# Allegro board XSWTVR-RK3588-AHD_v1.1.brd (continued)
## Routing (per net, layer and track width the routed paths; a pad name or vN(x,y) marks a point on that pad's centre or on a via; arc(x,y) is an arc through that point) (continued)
N17604223: length 3.4
  TOP w0.127: C345.2 78.73,20.72 U25.1
N17604225: length 3.1
  TOP w0.127: C346.1 78.08,16.91 U25.4
N17604227: length 3.1
  TOP w0.127: U25.5 78.08,15.64 C346.2
N17604259: length 2.2
  TOP w0.127: U25.2 79.3,19.45 C347.2
N17604261: length 2.2
  TOP w0.127: C348.1 78.82,14.37 U25.6
N17613828: length 2.1
  TOP w0.127: R308.1 78.89,13.1 U25.7
N17613831: length 2.2
  TOP w0.127: U25.8 79,11.83 R309.1
N17622103: length 35.2
  BOTTOM w0.127: R66.1 30.41,33.19 30.41,38.02 30.96,38.57 35.18,38.57 35.57,38.18 42.75,38.18 49.94,45.36 49.94,47.09 50.25,47.4 Q3.1 52.37,47.4 R64.2 52.69,47.54 C108.2
N17622132: length 1.1
  BOTTOM w0.127: R66.2 31.49,30.66 Q5.3
N17622163: length 3.4
  BOTTOM w0.127: 27.69,28.82 R68.2 ; 27.69,28.82 R70.1 C110.1 ; 27.69,28.82 28.88,28.82 Q5.1
N17627462: length 1.8
  TOP w0.127: R129.2 77.65,138.72 77.65,138.72 U14.44
N17719071: length 2.3
  TOP w0.127: R2.1 42.98,48.84 U1.59
N17720124: length 2.9
  TOP w0.127: SW1.1 38.85,100.52 38.85,101.89 R1.2
N17720923: length 2.6
  TOP w0.381: R305.2 R304.1 55.46,130.28 Q30.1
N17726410: length 4.8
  TOP w0.203: R258.2 54.49,113.65 C325.1 53.49,112.73 R257.1 53.13,113.09 53.13,113.96 C329.1 54.17,113.97 R258.2
N17726460: length 1.8
  TOP w0.203: C326.2 52,115.17 U23.22
N17726498: length 3.8
  TOP w0.203: C328.2 52.24,113.41 C329.2 50.25,113.97 49.95,114.27 U23.21
N17732255: length 4.6
  BOTTOM w0.127: R63.2 12.9,40.23 13.42,39.7 Q2.1 ; R63.2 12.06,40.22 R65.1 ; R63.2 11.12,40.23 C106.2
N17732284: length 1.7
  BOTTOM w0.127: R65.2 12.06,37.5 Q4.3
N17732315: length 3.7
  BOTTOM w0.127: Q4.1 17.31,38.45 R69.1 17.76,37.99 C109.1 19.68,37.99 R67.2
N17733329: length 1.8
  TOP w0.127: U8.23 105.17,30.85 105.18,30.86 R39.1
N17735210: length 7.6
  TOP w0.127: R253.2 19.33,23.41 17.69,23.41 17.51,23.23 D31.1 17.5,22.89 J22.2
N17735212: length 7.9
  TOP w0.127: J22.3 17.5,23.99 D30.1 17.51,24.54 17.68,24.72 19.12,24.72 R254.2
N17735222: length 7.8
  TOP w0.127: R256.2 19.27,30.03 17.63,30.03 17.51,29.91 D27.1 17.07,29.44 17.02,29.49 13.93,29.49 13.92,29.49 J22.8
N17735246: length 7.6
  TOP w0.127: R252.2 19.31,22.33 17.75,22.33 17.51,22.09 D32.1 17.5,21.79 J22.1
N17735252: length 7.8
  TOP w0.127: J22.5 17.46,26.19 D29.1 17.51,26.72 17.63,26.85 18.95,26.85 19.63,26.17 R359.2
N17735257: length 7.8
  TOP w0.127: R255.2 19.26,28.93 17.63,28.93 17.51,28.8 D28.1 17.46,28.39 J22.7
N17791454: length 3.6
  TOP w0.203: 48.15,114.02 U23.17
  TOP w0.508: FB28.2 48.15,111.06 C335.1 C334.1 48.15,114.02
N17887677: length 9.4
  TOP w0.254: D41.3 64.13,151.37 61.32,151.37 60.22,150.26 R323.1
N17887693: length 5.6
  TOP w0.254: D41.1 64.28,149.01 63.18,149.01 61.2,147.03 R324.1
N17891340: length 1.7
  TOP w0.127: R329.2 34.46,76.8 U28.8
N17893373: length 2.3
  TOP w0.127: R330.2 35.36,78.57 R331.1 35.35,77.6 U28.10
N17901873: length 2.8
  TOP w0.127: R44.2 65.06,23.66 R43.2 67.66,23.66 U9.13
N17901877: length 2.8
  TOP w0.127: U9.12 67.63,24.66 R43.1 65.07,24.66 R45.2
N17904447: length 2.8
  TOP w0.127: U10.13 80.6,23.86 R333.2 78.04,23.86 R332.2
N17904489: length 2.8
  TOP w0.127: R334.2 78.04,24.86 R333.1 80.71,24.86 U10.12
N17906339: length 2.8
  TOP w0.127: R335.2 78.05,33.69 R336.2 80.68,33.69 U26.13
N17906381: length 2.8
  TOP w0.127: U26.12 80.64,34.69 R336.1 78.05,34.69 R337.2
N17907326: length 2.9
  TOP w0.127: R338.2 75.8,38.46 75.76,38.42 R339.2 75.02,38.65 U29.13
N17907351: length 2.8
  TOP w0.127: U29.12 73.46,37.42 R339.1 75.78,37.42 75.8,37.44 R340.2
N17918762: length 3.4
  TOP w0.127: D44.1 115.35,14.14 114.83,14.66 R342.1 114.83,16.6 R341.2
N17918800: length 3.5
  TOP w0.127: R342.2 113.36,16.08 111.24,16.08 111.04,15.88 Q31.1
N17919694: length 5.6
  BOTTOM w0.127: Q32.1 26.48,35.96 26.48,33.03 C376.2 27.7,31.82 R344.2
N17920327: length 2.9
  TOP w0.381: R346.2 95.71,31.73 C377.2 96.37,31.73 97.03,32.38 Q33.1
N17947557: length 7.9
  TOP w0.203: R134.2 89.08,147.31 89.65,147.89 91.02,147.89 91.92,148.79 91.92,151.5 D43.4
N17948062: length 4.5
  TOP w0.203: D43.2 89.12,148.59 88.57,148.59 87.77,147.79 R348.2
N18031326: length 6.3
  TOP w0.127: R206.1 152.75,82.11 151.42,83.45 151.42,86.26 151,86.67 U19.31
N18177282: length 1.5
  TOP w0.127: U9.7 74.5,29.89 R351.2
N18177600: length 1.8
  TOP w0.127: R353.2 88.25,30.02 U10.7
N18177766: length 2
  TOP w0.127: R355.2 87.34,40.47 86.79,39.92 U26.7
N18177976: length 1.7
  TOP w0.102: U29.7 66.53,32.3 66.52,32.29 R357.2
N18179902: length 1.6
  TOP w0.305: C378.1 27.76,30.72 27.75,30.71 U22.1
N18180321: length 3.8
  TOP w0.127: U22.9 24.06,28.07 22.82,29.32 22.82,30.56 R250.2
N18180375: length 4.9
  TOP w0.127: R248.2 21.8,30.44 22.08,30.16 22.08,28.98 23.99,27.07 U22.11
N18180517: length 1.6
  TOP w0.127: U22.14 25.75,25.31 25.9,25.15 R360.2
N18180676: length 1.6
  TOP w0.254: C379.2 26.77,25.3 26.75,25.33 U22.16
N25391738: length 7.5
  TOP w0.203: C343.1 41.35,118.01 41.35,116.92 42.09,116.18 46.56,116.18 U23.12
N25392270: length 2.3
  TOP w0.203: C339.1 49.57,113.26 49.05,113.78 U23.19
N25392272: length 4.3
  TOP w0.254: U23.10 45.49,116.97 44.42,118.04 C340.1
N25392276: length 2.6
  TOP w0.203: C338.1 49.5,114.02 U23.20
N25392525: length 6.8
  TOP w0.203: C344.1 41.74,118.02 41.74,117.1 42.32,116.52 U23.11
N25392529: length 1.8
  TOP w0.127: R260.2 50.54,119.63 49.95,119.04 U23.1
N25392543: length 1.8
  TOP w0.127: R261.2 48.15,119.45 U23.5
N25392545: length 1.6
  TOP w0.127: R262.2 47.7,119.98 47.7,119.17 47.7,119.17 U23.6
N25392559: length 1.8
  TOP w0.127: U23.7 47.25,119.42 R263.2
N25392573: length 2.8
  TOP w0.127: U23.8 46.19,117.87 45.67,118.39 45.67,119.98 R264.2
N25392575: length 1.7
  TOP w0.127: R265.2 52.2,117.87 U23.28
N25392589: length 1.9
  TOP w0.127: R266.2 51.66,117.42 U23.27
N174312303: length 2.1
  TOP w0.203: R25.2 146.39,62.67 146.69,62.37 146.69,61.95 146.2,61.46 U5.4
N175432600: length 1.8
  TOP w0.203: R134.1 90.08,146.73 90.32,146.49 Q12.3

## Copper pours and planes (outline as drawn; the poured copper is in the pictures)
DGND on TOP: 0.51,156 1.53,158.47 4,159.49 155.78,159.49 158.25,158.47 159.27,156 159.27,4 158.25,1.53 155.78,0.51 4,0.51 1.53,1.53 0.51,4 ; 72 cut-outs
DGND on BOTTOM: 155.78,159.49 158.25,158.47 159.27,156 159.27,4 158.25,1.53 155.78,0.51 4,0.51 1.53,1.53 0.51,4 0.51,156 1.53,158.47 4,159.49 ; 48 cut-outs
DGND on GND02, POW04, GND05: 155.78,159.49 158.25,158.47 159.27,156 159.27,4 158.25,1.53 155.78,0.51 4,0.51 1.53,1.53 0.51,4 0.51,156 1.53,158.47 4,159.49
DGND on L3: 0.51,156 1.53,158.47 4,159.49 155.78,159.49 158.25,158.47 159.27,156 159.27,4 158.25,1.53 155.78,0.51 4,0.51 1.53,1.53 0.51,4 ; 21 cut-outs
VCC1V2 on TOP: 57.83,20.14 54.26,20.14 54.07,19.95 54.07,18.38 54.25,18.19 57.49,18.19 57.91,17.78 57.91,15.17 58.78,14.29 58.78,12.14 58.96,11.97 60.85,11.97 61.01,12.12 61.01,14.37 61.82,15.18 61.82,20.37 61.67,20.52 58.21,20.52
VCC1V2 on BOTTOM: 55.45,20.07 54.26,20.07 54.14,19.95 54.14,18.73 54.28,18.59 55.51,18.59 55.56,18.64 55.56,19.96
VCC3V3_SYS on TOP: 61.85,14.54 61.61,14.3 61.61,12.06 61.71,11.95 63.01,11.95 63.11,12.05 63.11,12.73 63.28,12.9 67.29,12.9 67.58,13.19 67.58,15.64 67.41,15.81 65.65,15.81 65.54,15.7 65.54,14.77 65.54,14.76 65.54,14.71 65.37,14.54
VCC3V3_SYS on TOP: 1.03,104.53 0.89,104.4 0.89,101.89 1.01,101.77 6.49,101.77 6.64,101.92 6.64,102.91 6.87,103.13 7.88,103.13 8.01,103.26 8.01,104.41 7.89,104.53
VCC3V3_SYS on BOTTOM: 145.19,39.74 143.01,39.74 142.16,38.88 142.16,37.45 142.38,37.22 144.77,37.22 145.23,37.68 145.23,39.7
VCC3V3_SYS on BOTTOM: 54.99,22 52.99,22 52.92,21.92 52.92,20.79 53,20.71 54.96,20.71 55.04,20.79 55.04,21.95
VCC3V3_SYS on BOTTOM: 139.49,22.09 139.49,20.93 139.41,20.85 137.45,20.85 137.37,20.93 137.37,22.06 137.44,22.14 139.44,22.14
VCC3V3_SYS on BOTTOM: 57.95,33.22 56.81,33.22 56.75,33.16 56.75,31.44 56.83,31.36 57.99,31.36 58.06,31.43 58.06,33.11
VCC3V3_SYS on BOTTOM: 142.55,32.3 142.55,30.63 142.48,30.55 141.32,30.55 141.24,30.63 141.24,32.35 141.3,32.41 142.44,32.41
VCC3V3_SYS on BOTTOM: 149.47,69.07 149.49,69.07 152.64,69.07 152.96,68.75 152.96,67.25 152.96,67.25 153.18,67.03 153.82,67.03 154.49,66.36 154.49,65.08 154.1,64.69 152.39,64.69 152.15,64.93 152.14,66.64 151.65,67.08 149.57,67.08 149.39,67.26 149.39,68.99
VCC3V3_SYS on BOTTOM: 57.28,46.9 50.67,46.9 50.4,46.64 50.4,44.97 50.52,44.85 57.31,44.85 57.61,45.15 57.61,46.58
VCC3V3_SYS on BOTTOM: 7.86,104.65 3.84,104.65 3.71,104.51 3.71,103.2 3.85,103.06 7.91,103.06 8,103.15 8,104.5
VCC3V3_SYS on L3: 148.36,86.77 153.91,86.77 157.83,82.85 157.83,17.64 152.67,12.49 109.51,12.49 105.54,8.52 93.02,8.52 89.05,12.49 80.13,12.49 80.12,12.47 22.54,12.47 19.78,15.23 5.65,15.23 2.21,18.67 2.21,66.12 2.58,66.49 9.52,66.49 9.52,66.5 14.53,66.5 16.97,64.06 16.97,50.57 14.3,47.89 11.08,47.89 10.73,47.55 10.73,22.13 11.93,20.94 19.77,20.94 53.09,20.94 57.82,25.66 69.36,25.66 69.87,25.15 80.8,25.15 81.44,25.78 82.3,25.78 84.98,25.78 85.08,25.9 97.24,25.9 101.92,30.58 127.16,30.58 136.37,39.8 149.31,39.8 150.41,40.9 150.43,52.63 147.02,56.04 147.02,85.43
VCC3V3_SYS on POW04: 1.84,104.49 7.91,104.49 8.46,103.94 8.46,78.42 9.75,77.12 13.44,77.12 15.1,75.47 15.1,67.71 9,61.62 7.55,61.62 7.53,61.6 2.29,61.6 1.36,62.53 1.36,104.02
VCC3V9_5G on TOP: 111.62,61.19 109.54,61.19 109.32,60.98 109.32,57.63 109.51,57.44 112.38,57.44 117.97,63.03 117.97,70.87 117.88,70.95 114.31,70.95 114.25,70.89 114.25,63.81
VCC3V9_5G on BOTTOM: 9.47,47.5 12.86,47.5 12.86,47.14 14.79,45.22 14.79,44.4 14.73,44.34 14.73,41.48 14.49,41.23 12.79,41.23 12.58,41.44 12.58,44.35 12.32,44.6 9.52,44.6 9.3,44.81 9.3,47.33
VCC3V9_5G on POW04: 116.34,63.56 113.09,63.56 109.53,60.01 22.47,60.01 9.63,47.16 9.63,44.59 10.03,44.18 17.11,44.18 25.01,52.08 112.38,52.08 116.64,56.35 116.64,63.26
VCC5V0_SYS on TOP: 36.13,63.24 36.13,61.27 35.49,60.64 35.49,59.51 35.64,59.37 37.78,59.37 38.14,59.73 38.14,60.36 38.22,60.44 38.91,60.44 38.91,61.45 37.33,63.03 37.33,63.25 36.14,63.25
VCC5V0_SYS on TOP: 120.93,47.79 125.72,47.79 125.73,45.25 120.9,45.25 120.46,45.69 120.46,47.79
VCC5V0_SYS on POW04: 17.13,68.39 33.59,68.39 36.58,65.44 36.58,63.67 36.58,63.67 36.58,62.99 36.59,61.09 37.97,59.7 37.97,59.36 35.67,59.36 34.51,60.52 22.26,60.52 9.11,47.36 9.11,43.29 15.11,37.28 23.24,37.28 28.56,42.6 52.58,42.6 56.07,46.1 115.67,46.1 122.32,52.75 139.95,52.75 140.61,52.08 140.61,30.8 137.12,27.31 101.29,27.31 99.96,25.98 99.96,16.55 99.3,15.88 97.3,15.88 97.3,17.25 92.9,21.66 12.14,21.66 1.65,32.15 1.65,59.17 3.21,60.73 9.46,60.73
VCC_1V8 on TOP: 13.2,103.16 8.15,103.16 7.96,102.98 7.07,102.98 6.89,102.8 6.89,101.78 6.96,101.71 10.41,101.71 10.52,101.6 10.52,100.32 10.5,100.3 10.69,100.11 13.08,100.11 13.28,100.3 13.28,103.09
VCC_1V8 on BOTTOM: 13.27,103.17 10.64,103.17 10.54,103.06 10.54,100.3 10.69,100.15 13.22,100.15 13.45,100.38 13.45,102.99
VCC_1V8 on POW04: 9.42,100.63 9.81,100.24 13.4,100.24 13.92,100.77 13.92,102.74 30.26,119.07 54.83,119.07 55.35,119.6 55.35,129.17 42.37,142.15 37.3,142.14 9.42,114.25
VCC_DCIN on TOP: 158.56,62 148.25,62 147.95,61.7 147.95,60.38 147.13,59.56 144.93,59.56 144.84,59.47 144.84,58.57 144.91,58.5 158.5,58.5 158.81,58.81 158.81,61.75
VCC_DCIN on TOP: 158.66,72.72 148.35,72.72 148.05,72.42 148.05,71.1 147.23,70.29 145.03,70.29 144.93,70.2 144.93,69.3 145.01,69.22 158.6,69.22 158.84,69.46 158.84,72.54
VCC_DCIN on TOP: 14.26,116.69 13.86,116.29 13.86,111.81 14.26,111.41 22.49,111.41 23.65,110.25 25.75,110.25 28.39,112.89 37.13,112.89 38.56,111.46 38.56,107.69 37.87,107 36.05,107 35.92,106.87 35.92,105.92 36,105.84 41.14,105.84 41.19,105.89 41.19,114.05 38.55,116.69 34.12,116.69 34.11,116.69
VCC_DCIN on BOTTOM: 87.52,8.15 77.88,8.15 77.57,7.84 77.57,4.93 77.78,4.73 87.64,4.73 87.78,4.87 87.78,7.89
VCC_DCIN on BOTTOM: 68.29,8.14 58.65,8.14 58.34,7.83 58.34,4.92 58.54,4.72 68.4,4.72 68.55,4.86 68.55,7.88
VCC_DCIN on BOTTOM: 106.78,8.13 97.14,8.13 96.83,7.82 96.83,4.91 97.03,4.71 106.89,4.71 107.03,4.85 107.03,7.87
VCC_DCIN on BOTTOM: 10.71,15.45 8.26,15.45 7.99,15.18 7.99,5.1 8.33,4.76 10.69,4.76 10.92,4.98 10.92,15.24
VCC_DCIN on BOTTOM: 126.04,8.14 116.4,8.14 116.09,7.83 116.09,4.92 116.3,4.72 126.16,4.72 126.3,4.86 126.3,7.88
VCC_DCIN on BOTTOM: 145.28,8.16 135.63,8.16 135.32,7.85 135.32,4.94 135.53,4.74 145.39,4.74 145.53,4.88 145.53,7.9
VCC_DCIN on BOTTOM: 49.05,8.21 39.4,8.21 39.1,7.9 39.1,5 39.3,4.79 49.16,4.79 49.3,4.93 49.3,7.95
VCC_DCIN on BOTTOM: 29.8,8.15 20.16,8.15 19.85,7.84 19.85,4.93 20.06,4.73 29.92,4.73 30.06,4.87 30.06,7.89
VCC_DCIN on POW04: outline of 85 points within 7.75,4.58 157.65,122.98
VCC_IN on TOP: 16.12,130.13 3.82,130.12 3.15,129.41 3.15,118.37 3.52,118.01 17.33,118.01 17.64,118.32 17.64,122.29 17.42,122.52 9.46,122.52 9.17,122.8 9.17,125.1 9.47,125.39 16.29,125.39 16.48,125.58 16.49,129.72
VCCA1V8_CODEC on TOP: 49.58,119.53 48.99,119.53 48.9,119.45 48.9,118.18 48.97,118.11 49.57,118.11 49.65,118.19 49.65,119.46
VDD10_PHY0 on TOP: 129.7,82.19 127.03,82.19 126.92,82.09 126.92,81.14 127.04,81.03 128.14,81.03 128.35,80.82 128.35,78.88 128.41,78.82 129.96,78.82 130.03,78.9 130.03,81.86
VDD10_PHY1 on TOP: 151.5,82.34 149.13,82.34 149.08,82.29 149.08,80.64 149.18,80.54 151.45,80.54 151.57,80.67 151.57,82.27
5G_3V9 on BOTTOM: 17.87,48.52 19.99,48.53 20.47,48.06 23.43,48.06 23.45,48.03 23.45,46.52 21.35,44.42 21.35,42.77 18.97,40.39 18.97,39.86 18.74,39.64 15.51,39.64 15.42,39.73 15.42,41.03 15.55,41.16 17.55,41.16 17.55,41.16 17.87,41.48 17.87,48.39
5G_3V9 on BOTTOM: 39.6,48.48 39.6,46.53 39.66,46.47 41.29,46.47 42.52,47.7 43.46,47.7 43.46,47.71 47.3,47.71 47.85,48.25 51.68,48.25 51.94,48.51 51.94,50.19 51.66,50.47 41.6,50.47
5G_3V9 on POW04: 52.01,50.47 25.94,50.47 16.75,41.28 16.75,39.61 17.03,39.33 21.35,39.33 28.95,46.93 51.81,46.93 52.19,47.31 52.19,50.3
PHY0_REG_OUT on TOP: 127.85,86.35 127.52,86.35 127.51,86.33 127.51,84.92 126.99,84.4 126.99,83.62 127.07,83.53 129.01,83.53 129.1,83.63 129.1,85.09
PHY1_REG_OUT on TOP: 149.94,86.42 149.55,86.42 149.51,86.38 149.51,85.15 149.07,84.71 149.07,83.74 149.19,83.62 151.09,83.62 151.21,83.73 151.21,85.15
N17430388 on TOP: 29.15,109.75 20.52,109.75 19.97,109.2 19.97,104.98 20.38,104.57 32.05,104.57 32.2,104.72 32.2,105.7 32.08,105.83 30.18,105.83 29.53,106.48 29.53,109.37
N17430409 on TOP: 13.76,107.92 1.45,107.92 1.17,107.64 1.17,104.9 1.36,104.72 16.53,104.72 16.8,104.99 16.8,108.08 16.54,108.34 14.18,108.34
N17430974 on TOP: 140.91,58.16 135.51,58.16 135.01,58.66 135.01,60.76 134.56,61.21 130.26,61.21 130.04,60.99 130.04,54.48 130.4,54.11 140.87,54.11 141.12,54.37 141.12,57.95
N17430995 on TOP: 126.46,61.7 122.05,61.7 121.8,61.45 121.8,49.62 121.6,49.42 120.5,49.42 120.43,49.35 120.43,48.37 120.51,48.29 124.36,48.29 126.64,50.57 126.64,61.52
N17445910 on TOP: 141.14,68.91 132.32,68.91 132.09,68.69 132.09,66.29 132.29,66.08 141.11,66.08 141.26,66.23 141.26,68.79
N17445924 on TOP: 113.94,74.05 113.94,71.62 114.14,71.42 135.91,71.42 136.14,71.66 136.14,74.07 135.92,74.3 114.19,74.3
N18115892 on BOTTOM: 144.46,46.95 144.46,45.23 143.33,44.1 143.33,42.88 143.45,42.76 145.26,42.76 145.26,40.67 145.07,40.49 141.23,40.49 140.82,40.9 140.82,45.41 142.36,46.96 144.45,46.96
N18121133 on BOTTOM: 147.95,67.37 147.42,66.84 144.62,66.84 144.35,66.56 144.35,64.62 144.5,64.47 144.5,63.14 144.4,63.04 142.8,63.04 142.52,63.31 142.52,68.03 142.66,68.17 143.66,68.17 143.67,68.16 143.96,68.16 144.35,68.55 144.35,69.09 147.91,69.09 147.95,69.05

Small or netless copper shapes (teardrops, artwork), in the pictures only: 264 on TOP, 7 on BOTTOM, 2 on POW04

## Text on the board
Ref Des/Silkscreen Top: XSWTVR-RK3588-AHD | 2024-08-01 | V1.1
User.5: FIGURE | FINISHED_SIZE | 8.0 | 12.0 | 15.748 | 25.591 | 26.0 | 27.598 | 39.37 | 43.307 | 45.276 | 59.055 | 62.992 | 125.984 | 137.79 | 137.795 | 40.0 | 66.929x35.429 | 86.598x35.402 | 106.299x35.433 | DRILL CHART: TOP to BOTTOM | ALL UNITS ARE IN MILS | PLATED | NON-PLATED | QTY | 3161 | 733 | 32 | 4 | 8 | 18 | 16 | 56 | 24 | 2 | 1
